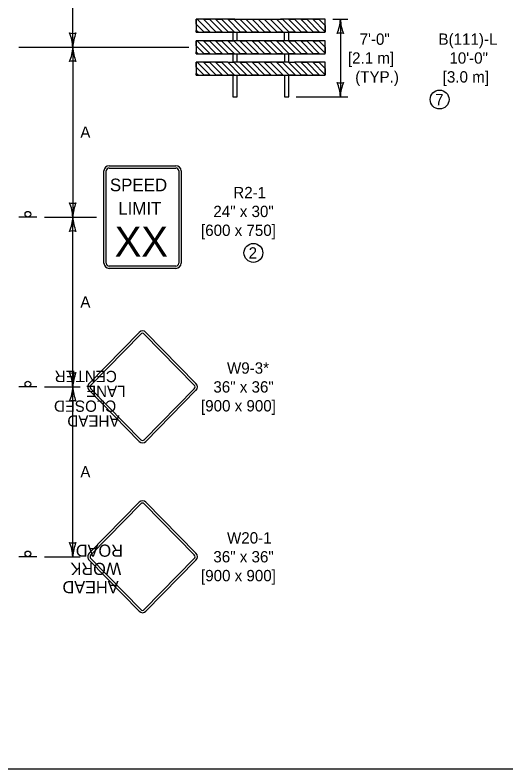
# Model space of a CAD drawing. Extents: x 49991.4 to 50021, y 49987.6 to 50011.4.
# Drawn here: x 50003.8 to 50006.402, y 50000.062 to 50004.057 of the extents above; entities that cross this region are included whole.
import ezdxf

# ---------------------------------------------------------------- set-up
doc = ezdxf.new("R2010")
doc.units = 0
for name, color, linetype in [('Level 1', 7, 'Continuous'), ('Level 2', 7, 'Continuous'), ('Level 3', 7, 'Continuous')]:
    doc.layers.add(name, color=color, linetype=linetype)

msp = doc.modelspace()

# ---------------------------------------------------------------- linework, layer by layer
at = {"layer": 'Level 1'}
for p, q in [((50004.8021, 50003.9666), (50004.7603, 50004.0084)), ((50004.8021, 50003.9666), (50004.7603, 50004.0084)), ((50004.8343, 50003.9666), (50004.7659, 50004.035)), ((50004.7659, 50004.035), (50004.8343, 50003.9666)), ((50004.8665, 50003.9666), (50004.7981, 50004.035)), ((50004.8665, 50003.9666), (50004.7981, 50004.035)), ((50004.8988, 50003.9666), (50004.8304, 50004.035)), ((50004.8304, 50004.035), (50004.8988, 50003.9666)), ((50004.931, 50003.9666), (50004.8626, 50004.035)), ((50004.931, 50003.9666), (50004.8626, 50004.035)), ((50004.9633, 50003.9666), (50004.8949, 50004.035)), ((50004.8949, 50004.035), (50004.9633, 50003.9666)), ((50004.9955, 50003.9666), (50004.9271, 50004.035)), ((50005.0277, 50003.9666), (50004.9593, 50004.035)), ((50004.9593, 50004.035), (50004.9992, 50004.035)), ((50004.9797, 50004.035), (50005.2248, 50004.035)), ((50005.0599, 50003.9666), (50004.9915, 50004.035)), ((50005.0921, 50003.9666), (50005.0237, 50004.035)), ((50005.1243, 50003.9666), (50005.0559, 50004.035)), ((50005.1565, 50003.9666), (50005.0881, 50004.035)), ((50005.1888, 50003.9666), (50005.1204, 50004.035)), ((50005.221, 50003.9666), (50005.1526, 50004.035)), ((50005.2534, 50003.9666), (50005.185, 50004.035)), ((50005.2391, 50004.035), (50005.2078, 50004.035)), ((50005.2857, 50003.9666), (50005.2173, 50004.035)), ((50005.3179, 50003.9666), (50005.2495, 50004.035)), ((50005.3179, 50003.9666), (50005.2495, 50004.035)), ((50005.3501, 50003.9666), (50005.2817, 50004.035)), ((50005.2817, 50004.035), (50005.3501, 50003.9666)), ((50005.3824, 50003.9666), (50005.314, 50004.035)), ((50005.3824, 50003.9666), (50005.314, 50004.035)), ((50005.4146, 50003.9666), (50005.3462, 50004.035)), ((50005.3462, 50004.035), (50005.4146, 50003.9666)), ((50005.4443, 50003.9691), (50005.3784, 50004.035)), ((50005.4443, 50003.9691), (50005.3784, 50004.035)), ((50005.4443, 50004.0014), (50005.4107, 50004.035)), ((50005.4107, 50004.035), (50005.4443, 50004.0014)), ((50004.7698, 50003.9666), (50004.7603, 50003.9761)), ((50004.7603, 50003.9761), (50004.7698, 50003.9666)), ((50004.9769, 50003.921), (50004.9769, 50003.9666)), ((50005.2277, 50003.921), (50005.2277, 50003.9666)), ((50004.8343, 50003.8526), (50004.7659, 50003.921)), ((50004.7659, 50003.921), (50004.8343, 50003.8526)), ((50004.8665, 50003.8526), (50004.7981, 50003.921)), ((50004.8665, 50003.8526), (50004.7981, 50003.921)), ((50004.8988, 50003.8526), (50004.8304, 50003.921)), ((50004.8304, 50003.921), (50004.8988, 50003.8526)), ((50004.931, 50003.8526), (50004.8626, 50003.921)), ((50004.931, 50003.8526), (50004.8626, 50003.921)), ((50004.9633, 50003.8526), (50004.8949, 50003.921)), ((50004.8949, 50003.921), (50004.9633, 50003.8526)), ((50004.9655, 50003.8827), (50004.9271, 50003.921)), ((50004.9655, 50003.9149), (50004.9593, 50003.921)), ((50005.06, 50003.8526), (50004.9916, 50003.921)), ((50005.0922, 50003.8526), (50005.0238, 50003.921)), ((50005.1245, 50003.8526), (50005.0561, 50003.921)), ((50005.1567, 50003.8526), (50005.0883, 50003.921)), ((50005.1889, 50003.8526), (50005.1205, 50003.921)), ((50005.2212, 50003.8526), (50005.1528, 50003.921)), ((50005.2534, 50003.8526), (50005.185, 50003.921)), ((50005.2857, 50003.8526), (50005.2173, 50003.921)), ((50005.3179, 50003.8526), (50005.2495, 50003.921)), ((50005.3179, 50003.8526), (50005.2495, 50003.921)), ((50005.3501, 50003.8526), (50005.2817, 50003.921)), ((50005.2817, 50003.921), (50005.3501, 50003.8526)), ((50005.3824, 50003.8526), (50005.314, 50003.921)), ((50005.3824, 50003.8526), (50005.314, 50003.921)), ((50005.4146, 50003.8526), (50005.3462, 50003.921)), ((50005.3462, 50003.921), (50005.4146, 50003.8526)), ((50005.4443, 50003.8552), (50005.3784, 50003.921)), ((50005.4443, 50003.8552), (50005.3784, 50003.921)), ((50005.4443, 50003.8874), (50005.4107, 50003.921)), ((50005.4107, 50003.921), (50005.4443, 50003.8874)), ((50004.8021, 50003.8526), (50004.7603, 50003.8944)), ((50004.8021, 50003.8526), (50004.7603, 50003.8944)), ((50005.0277, 50003.8526), (50004.9655, 50003.9149)), ((50004.9955, 50003.8526), (50004.9655, 50003.8827)), ((50004.7698, 50003.8526), (50004.7603, 50003.8622)), ((50004.7603, 50003.8622), (50004.7698, 50003.8526)), ((50004.8343, 50003.7387), (50004.7659, 50003.8071)), ((50004.7659, 50003.8071), (50004.8343, 50003.7387)), ((50004.8665, 50003.7387), (50004.7981, 50003.8071)), ((50004.8665, 50003.7387), (50004.7981, 50003.8071)), ((50004.8988, 50003.7387), (50004.8304, 50003.8071)), ((50004.8304, 50003.8071), (50004.8988, 50003.7387)), ((50004.931, 50003.7387), (50004.8626, 50003.8071)), ((50004.931, 50003.7387), (50004.8626, 50003.8071)), ((50004.9633, 50003.7387), (50004.8949, 50003.8071)), ((50004.8949, 50003.8071), (50004.9633, 50003.7387)), ((50004.9955, 50003.7387), (50004.9271, 50003.8071)), ((50004.9955, 50003.7387), (50004.9271, 50003.8071)), ((50005.0277, 50003.7387), (50004.9593, 50003.8071)), ((50004.9593, 50003.8071), (50005.0277, 50003.7387)), ((50005.06, 50003.7387), (50004.9916, 50003.8071)), ((50005.06, 50003.7387), (50004.9916, 50003.8071)), ((50005.0922, 50003.7387), (50005.0238, 50003.8071)), ((50005.0238, 50003.8071), (50005.0922, 50003.7387)), ((50005.1245, 50003.7387), (50005.0561, 50003.8071)), ((50005.1245, 50003.7387), (50005.0561, 50003.8071)), ((50005.1567, 50003.7387), (50005.0883, 50003.8071)), ((50005.0883, 50003.8071), (50005.1567, 50003.7387)), ((50005.1889, 50003.7387), (50005.1205, 50003.8071)), ((50005.1889, 50003.7387), (50005.1205, 50003.8071)), ((50005.2212, 50003.7387), (50005.1528, 50003.8071)), ((50005.1528, 50003.8071), (50005.2212, 50003.7387)), ((50005.2534, 50003.7387), (50005.185, 50003.8071)), ((50005.2534, 50003.7387), (50005.185, 50003.8071)), ((50005.2857, 50003.7387), (50005.2173, 50003.8071)), ((50005.2173, 50003.8071), (50005.2857, 50003.7387)), ((50005.3179, 50003.7387), (50005.2495, 50003.8071)), ((50005.3179, 50003.7387), (50005.2495, 50003.8071)), ((50005.3501, 50003.7387), (50005.2817, 50003.8071)), ((50005.2817, 50003.8071), (50005.3501, 50003.7387)), ((50005.3824, 50003.7387), (50005.314, 50003.8071)), ((50005.3824, 50003.7387), (50005.314, 50003.8071)), ((50005.4146, 50003.7387), (50005.3462, 50003.8071)), ((50005.3462, 50003.8071), (50005.4146, 50003.7387)), ((50005.4443, 50003.7412), (50005.3784, 50003.8071)), ((50005.4443, 50003.7412), (50005.3784, 50003.8071)), ((50005.4443, 50003.7735), (50005.4107, 50003.8071)), ((50005.4107, 50003.8071), (50005.4443, 50003.7735)), ((50004.8021, 50003.7387), (50004.7603, 50003.7804)), ((50004.8021, 50003.7387), (50004.7603, 50003.7804)), ((50004.7698, 50003.7387), (50004.7603, 50003.7482)), ((50004.7603, 50003.7482), (50004.7698, 50003.7387)), ((50004.2982, 50003.2588), (50004.6527, 50003.2588)), ((50004.2982, 50003.2464), (50004.6527, 50003.2464)), ((50004.2711, 50002.7421), (50004.2711, 50003.2316)), ((50004.2835, 50002.7421), (50004.2835, 50003.2316)), ((50004.6675, 50003.2316), (50004.6675, 50002.7421)), ((50004.6799, 50003.2316), (50004.6799, 50002.7421)), ((50003.9157, 50002.9869), (50003.8197, 50002.9869)), ((50004.6527, 50002.7273), (50004.2982, 50002.7273)), ((50004.6527, 50002.7149), (50004.2982, 50002.7149)), ((50004.1922, 50002.105), (50004.4573, 50002.3757)), ((50004.201, 50002.0963), (50004.4662, 50002.367)), ((50004.4848, 50002.367), (50004.75, 50002.0963)), ((50004.4936, 50002.3757), (50004.7588, 50002.105)), ((50003.9157, 50002.0868), (50003.8197, 50002.0868)), ((50004.4573, 50001.7981), (50004.1922, 50002.0688)), ((50004.4662, 50001.8068), (50004.201, 50002.0775)), ((50004.75, 50002.0775), (50004.4848, 50001.8068)), ((50004.7588, 50002.0688), (50004.4936, 50001.7981)), ((50004.1922, 50001.2051), (50004.4573, 50001.4757)), ((50004.201, 50001.1964), (50004.4662, 50001.4671)), ((50004.4848, 50001.4671), (50004.75, 50001.1964)), ((50004.4936, 50001.4757), (50004.7588, 50001.2051)), ((50003.9157, 50001.1868), (50003.8197, 50001.1868)), ((50004.4573, 50000.8981), (50004.1922, 50001.1688)), ((50004.4662, 50000.9068), (50004.201, 50001.1775)), ((50004.75, 50001.1775), (50004.4848, 50000.9068)), ((50004.7588, 50001.1688), (50004.4936, 50000.8981))]:
    msp.add_line(p, q, dxfattribs=at)
msp.add_lwpolyline([(50008.6146, 50011.2628), (50000.3356, 50011.2628), (50000.3356, 50000.0624), (50008.6146, 50000.0624)], close=True, dxfattribs=at)
for points in [[(50004.9655, 50004.035), (50004.7603, 50004.035), (50004.7603, 50003.9666), (50004.9655, 50003.9666)], [(50004.7603, 50004.0084), (50004.7603, 50004.035), (50004.7659, 50004.035)], [(50004.7981, 50004.035), (50004.8304, 50004.035)], [(50004.8626, 50004.035), (50004.8949, 50004.035)], [(50005.0277, 50003.9666), (50004.9955, 50003.9666), (50004.9271, 50004.035), (50004.9593, 50004.035), (50005.0277, 50003.9666)], [(50004.9655, 50003.9666), (50005.4443, 50003.9666), (50005.4443, 50004.035), (50005.2391, 50004.035)], [(50004.9915, 50004.035), (50004.9992, 50004.035), (50005.0237, 50004.035), (50005.0921, 50003.9666), (50005.0599, 50003.9666), (50004.9915, 50004.035)], [(50005.0559, 50004.035), (50005.0881, 50004.035), (50005.1565, 50003.9666), (50005.1243, 50003.9666), (50005.0559, 50004.035)], [(50005.1204, 50004.035), (50005.1526, 50004.035), (50005.221, 50003.9666), (50005.1888, 50003.9666), (50005.1204, 50004.035)], [(50005.185, 50004.035), (50005.2078, 50004.035), (50005.2173, 50004.035), (50005.2857, 50003.9666), (50005.2534, 50003.9666), (50005.185, 50004.035)], [(50005.2495, 50004.035), (50005.2817, 50004.035)], [(50005.314, 50004.035), (50005.3462, 50004.035)], [(50005.3784, 50004.035), (50005.4107, 50004.035)], [(50005.4443, 50004.0014), (50005.4443, 50003.9691)], [(50004.7698, 50003.9666), (50004.7603, 50003.9666), (50004.7603, 50003.9761)], [(50004.8343, 50003.9666), (50004.8021, 50003.9666)], [(50004.8988, 50003.9666), (50004.8665, 50003.9666)], [(50004.9633, 50003.9666), (50004.931, 50003.9666)], [(50004.9541, 50003.9666), (50004.9541, 50003.921)], [(50005.2505, 50003.921), (50005.2505, 50003.9666)], [(50005.3501, 50003.9666), (50005.3179, 50003.9666)], [(50005.4146, 50003.9666), (50005.3824, 50003.9666)], [(50004.9655, 50003.921), (50004.7603, 50003.921), (50004.7603, 50003.8526), (50005.4443, 50003.8526), (50005.4443, 50003.921), (50004.9655, 50003.921)], [(50004.7603, 50003.8944), (50004.7603, 50003.921), (50004.7659, 50003.921)], [(50004.7981, 50003.921), (50004.8304, 50003.921)], [(50004.8626, 50003.921), (50004.8949, 50003.921)], [(50005.0277, 50003.8526), (50004.9955, 50003.8526), (50004.9655, 50003.8827), (50004.9271, 50003.921), (50004.9541, 50003.921), (50004.9593, 50003.921), (50004.9655, 50003.9149), (50005.0277, 50003.8526)], [(50004.9916, 50003.921), (50005.0238, 50003.921), (50005.0922, 50003.8526), (50005.06, 50003.8526), (50004.9916, 50003.921)], [(50005.0561, 50003.921), (50005.0883, 50003.921), (50005.1567, 50003.8526), (50005.1245, 50003.8526), (50005.0561, 50003.921)], [(50005.1205, 50003.921), (50005.1528, 50003.921), (50005.2212, 50003.8526), (50005.1889, 50003.8526), (50005.1205, 50003.921)], [(50005.185, 50003.921), (50005.2173, 50003.921), (50005.2857, 50003.8526), (50005.2534, 50003.8526), (50005.185, 50003.921)], [(50005.2495, 50003.921), (50005.2817, 50003.921)], [(50005.314, 50003.921), (50005.3462, 50003.921)], [(50005.3784, 50003.921), (50005.4107, 50003.921)], [(50005.4443, 50003.8874), (50005.4443, 50003.8552)], [(50004.7698, 50003.8526), (50004.7603, 50003.8526), (50004.7603, 50003.8622)], [(50004.8343, 50003.8526), (50004.8021, 50003.8526)], [(50004.8988, 50003.8526), (50004.8665, 50003.8526)], [(50004.9633, 50003.8526), (50004.931, 50003.8526)], [(50004.9541, 50003.8526), (50004.9541, 50003.8071)], [(50004.9769, 50003.8071), (50004.9769, 50003.8526)], [(50005.2277, 50003.8526), (50005.2277, 50003.8071)], [(50005.2505, 50003.8071), (50005.2505, 50003.8526)], [(50005.3501, 50003.8526), (50005.3179, 50003.8526)], [(50005.4146, 50003.8526), (50005.3824, 50003.8526)], [(50004.7603, 50003.7804), (50004.7603, 50003.8071), (50004.7659, 50003.8071)], [(50004.9271, 50003.8071), (50004.7603, 50003.8071), (50004.7603, 50003.7387), (50005.4443, 50003.7387), (50005.4443, 50003.8071), (50005.2817, 50003.8071)], [(50004.7981, 50003.8071), (50004.8304, 50003.8071)], [(50004.8626, 50003.8071), (50004.8949, 50003.8071)], [(50004.9271, 50003.8071), (50004.9593, 50003.8071)], [(50005.2495, 50003.8071), (50004.9593, 50003.8071)], [(50004.9916, 50003.8071), (50005.0238, 50003.8071)], [(50005.0561, 50003.8071), (50005.0883, 50003.8071)], [(50005.1205, 50003.8071), (50005.1528, 50003.8071)], [(50005.185, 50003.8071), (50005.2173, 50003.8071)], [(50005.2495, 50003.8071), (50005.2817, 50003.8071)], [(50005.314, 50003.8071), (50005.3462, 50003.8071)], [(50005.3784, 50003.8071), (50005.4107, 50003.8071)], [(50005.4443, 50003.7735), (50005.4443, 50003.7412)], [(50004.7698, 50003.7387), (50004.7603, 50003.7387), (50004.7603, 50003.7482)], [(50004.8343, 50003.7387), (50004.8021, 50003.7387)], [(50004.8988, 50003.7387), (50004.8665, 50003.7387)], [(50004.9633, 50003.7387), (50004.931, 50003.7387)], [(50004.9541, 50003.7386), (50004.9541, 50003.6246), (50004.9769, 50003.6246), (50004.9769, 50003.7386)], [(50005.0277, 50003.7387), (50004.9955, 50003.7387)], [(50005.0922, 50003.7387), (50005.06, 50003.7387)], [(50005.1567, 50003.7387), (50005.1245, 50003.7387)], [(50005.2212, 50003.7387), (50005.1889, 50003.7387)], [(50005.2277, 50003.7386), (50005.2277, 50003.6246), (50005.2505, 50003.6246), (50005.2505, 50003.7386)], [(50005.2857, 50003.7387), (50005.2534, 50003.7387)], [(50005.3501, 50003.7387), (50005.3179, 50003.7387)], [(50005.4146, 50003.7387), (50005.3824, 50003.7387)]]:
    msp.add_lwpolyline(points, dxfattribs=at)
for centre in [(50003.8676, 50003.002), (50003.8676, 50002.102), (50003.8676, 50001.202)]:
    msp.add_circle(centre, 0.0152, dxfattribs=at)
for centre, radius, start, end in [((50004.2982, 50003.2316), 0.0272, 90, 180), ((50004.2982, 50003.2316), 0.0148, 90, 180), ((50004.6527, 50003.2316), 0.0272, 0, 90), ((50004.6527, 50003.2316), 0.0148, 0, 90), ((50004.2982, 50002.7421), 0.0272, 180, 270), ((50004.2982, 50002.7421), 0.0148, 180, 270), ((50004.6527, 50002.7421), 0.0148, 270, 360), ((50004.6527, 50002.7421), 0.0272, 270, 360)]:
    msp.add_arc(centre, radius, start, end, dxfattribs=at)
for centre, major_axis, ratio, start_param, end_param in [((50004.4755, 50002.3575), (0, 0.0258), 0.98963, 5.497787, 7.068583), ((50004.4755, 50002.3575), (0, 0.0134), 0.98, 5.497787, 7.068583), ((50004.2103, 50002.0869), (0, 0.0258), 0.98963, 0.785394, 2.356194), ((50004.2103, 50002.0869), (0, 0.0134), 0.98, 0.785394, 2.356194), ((50004.7407, 50002.0869), (0, 0.0134), 0.98, 3.926991, 5.497787), ((50004.7407, 50002.0869), (0, 0.0258), 0.98963, 3.926991, 5.497787), ((50004.4755, 50001.8162), (0, -0.0134), 0.98, 5.497795, 7.068583), ((50004.4755, 50001.8162), (0, -0.0258), 0.98963, 5.497795, 7.068583), ((50004.4755, 50001.4575), (0, 0.0258), 0.98963, 5.497787, 7.068583), ((50004.4755, 50001.4575), (0, 0.0134), 0.98, 5.497787, 7.068583), ((50004.2102, 50001.1868), (0, 0.0258), 0.98963, 0.785394, 2.356194), ((50004.7407, 50001.1869), (0, 0.0258), 0.98963, 3.926991, 5.497787), ((50004.2102, 50001.1868), (0, 0.0134), 0.98, 0.785394, 2.356194), ((50004.7407, 50001.1869), (0, 0.0134), 0.98, 3.926991, 5.497787), ((50004.4755, 50000.9162), (0, -0.0258), 0.98963, 5.497795, 7.068583), ((50004.4755, 50000.9162), (0, -0.0134), 0.98, 5.497795, 7.068583)]:
    msp.add_ellipse(centre, major_axis=major_axis, ratio=ratio, start_param=start_param, end_param=end_param, dxfattribs=at)
at = {"layer": 'Level 2'}
for centre in [(50006.0506, 50003.6098), (50005.0632, 50002.7969)]:
    msp.add_circle(centre, 0.0501, dxfattribs=at)
at = {"layer": 'Level 3'}
for p, q in [((50004.1057, 50003.8868), (50004.1057, 50004.3368)), ((50005.4843, 50004.035), (50005.5643, 50004.035)), ((50005.5243, 50004.035), (50005.5243, 50003.6246)), ((50003.8197, 50003.8868), (50004.7203, 50003.8868)), ((50004.1057, 50003.8868), (50004.1057, 50002.9869)), ((50005.2905, 50003.6246), (50005.5643, 50003.6246)), ((50003.9557, 50002.9869), (50004.2311, 50002.9869)), ((50004.1057, 50002.0869), (50004.1057, 50002.9869)), ((50003.9557, 50002.0868), (50004.1448, 50002.0869)), ((50004.1057, 50001.1868), (50004.1057, 50002.0869)), ((50003.9557, 50001.1868), (50004.1447, 50001.1868))]:
    msp.add_line(p, q, dxfattribs=at)
for centre, radius, start, end in [((50005.3022, 50004.0441), 0.2223, 337.456, 357.6395), ((50005.757, 50004.0465), 0.233, 182.8273, 202.0772), ((50004.1057, 50004.0151), 0.0548, 252.1388, 287.8612), ((50003.873, 50003.8753), 0.233, 2.8273, 22.0772), ((50004.3278, 50003.8777), 0.2223, 157.456, 177.6395), ((50005.5243, 50003.9068), 0.0548, 72.1388, 107.8612), ((50003.8836, 50003.896), 0.2223, 337.456, 357.6395), ((50004.3384, 50003.8983), 0.233, 182.8273, 202.0772), ((50004.1057, 50003.7586), 0.0548, 72.1388, 107.8612), ((50005.5243, 50003.7528), 0.0548, 252.1388, 287.8612), ((50005.2916, 50003.6131), 0.233, 2.8273, 22.0772), ((50005.7464, 50003.6154), 0.2223, 157.456, 177.6395), ((50004.1057, 50003.1151), 0.0548, 252.1388, 287.8612), ((50003.873, 50002.9754), 0.233, 2.8273, 22.0772), ((50004.3278, 50002.9777), 0.2223, 157.456, 177.6395), ((50003.8836, 50002.996), 0.2223, 337.456, 357.6395), ((50004.3384, 50002.9983), 0.233, 182.8273, 202.0772), ((50004.1057, 50002.8586), 0.0548, 72.1388, 107.8612), ((50004.1057, 50002.2151), 0.0548, 252.1388, 287.8612), ((50003.873, 50002.0754), 0.233, 2.8273, 22.0772), ((50004.3278, 50002.0777), 0.2223, 157.456, 177.6395), ((50003.8836, 50002.096), 0.2223, 337.456, 357.6395), ((50004.3384, 50002.0983), 0.233, 182.8273, 202.0772), ((50004.1057, 50001.9586), 0.0548, 72.1388, 107.8612), ((50004.1057, 50001.3151), 0.0548, 252.1388, 287.8612), ((50003.873, 50001.1754), 0.233, 2.8273, 22.0772), ((50004.3278, 50001.1777), 0.2223, 157.456, 177.6395)]:
    msp.add_arc(centre, radius, start, end, dxfattribs=at)

# ---------------------------------------------------------------- texts
at = {"layer": 'Level 1'}
for s, height, p in [('SPEED', 0.06696, (50004.3024, 50003.1237)), ('LIMIT', 0.06696, (50004.3467, 50002.9999)), ('XX', 0.15775, (50004.3284, 50002.7779))]:
    msp.add_text(s, height=height, dxfattribs=at).set_placement(p)
for s, height, p in [('CENTER', 0.06, (50004.3393, 50002.1721)), ('LANE', 0.06, (50004.3854, 50002.0934)), ('CLOSED', 0.06, (50004.336, 50002.0148)), ('AHEAD', 0.06, (50004.3534, 50001.9361)), ('ROAD', 0.06453, (50004.3713, 50001.2514)), ('WORK', 0.06453, (50004.3623, 50001.1547)), ('AHEAD', 0.06453, (50004.3485, 50001.0579))]:
    msp.add_text(s, height=height, rotation=180, dxfattribs=at).set_placement(p)
at = {"layer": 'Level 2'}
for s, p in [('7\'-0"', (50005.6265, 50003.8998)), ('B(111)-L', (50006.0446, 50003.8998)), ('[2.1 m]', (50005.5643, 50003.7998)), ('10\'-0"', (50006.1024, 50003.7998)), ('(TYP.)', (50005.6031, 50003.6998)), ('[3.0 m]', (50006.0671, 50003.6998)), ('7', (50006.0268, 50003.5798)), ('R2-1', (50004.9567, 50003.0869)), ('24" x 30"', (50004.8511, 50002.9869)), ('[600 x 750]', (50004.7856, 50002.8869)), ('2', (50005.038, 50002.7669)), ('W9-3*', (50004.9233, 50002.1569)), ('36" x 36"', (50004.8511, 50002.0569)), ('[900 x 900]', (50004.7856, 50001.9569)), ('W20-1', (50004.9234, 50001.2569)), ('36" x 36"', (50004.8511, 50001.1569)), ('[900 x 900]', (50004.7856, 50001.0569))]:
    msp.add_text(s, height=0.06, dxfattribs=at).set_placement(p)
for p in [(50004.1457, 50003.4068), (50004.1457, 50002.5069), (50004.1457, 50001.6069)]:
    msp.add_text('A', height=0.06, rotation=360, dxfattribs=at).set_placement(p)

doc.saveas('drawing.dxf')
